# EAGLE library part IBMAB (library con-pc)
8-bit CARD IBM/PC-AT
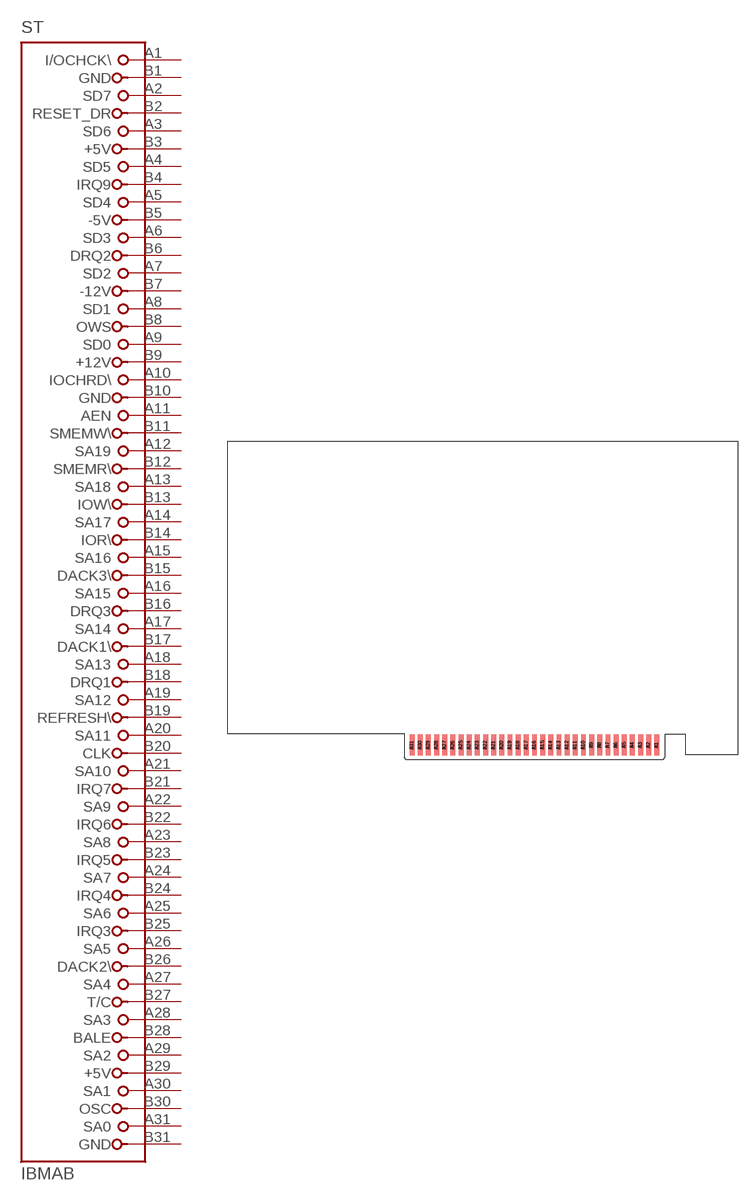
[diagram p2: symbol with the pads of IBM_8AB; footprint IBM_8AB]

Designator prefix ST

## IBMAB  [IBM_8AB]
A1  I/OCHCK\  in
A2  SD7
A3  SD6
A4  SD5
A5  SD4
A6  SD3
A7  SD2
A8  SD1
A9  SD0
A10  IOCHRD\  in
A11  AEN  out
A12  SA19
A13  SA18
A14  SA17
A15  SA16
A16  SA15
A17  SA14
A18  SA13
A19  SA12
A20  SA11
A21  SA10
A22  SA9
A23  SA8
A24  SA7
A25  SA6
A26  SA5
A27  SA4
A28  SA3
A29  SA2
A30  SA1
A31  SA0
B1  GND  pwr
B2  RESET_DR  out
B3  +5V  pwr
B4  IRQ9  in
B5  -5V  pwr
B6  DRQ2  in
B7  -12V  pwr
B8  OWS  in
B9  +12V  pwr
B10  GND  pwr
B11  SMEMW\  out
B12  SMEMR\  out
B13  IOW\
B14  IOR\
B15  DACK3\  out
B16  DRQ3  in
B17  DACK1\  out
B18  DRQ1  in
B19  REFRESH\
B20  CLK  out
B21  IRQ7  in
B22  IRQ6  in
B23  IRQ5  in
B24  IRQ4  in
B25  IRQ3  in
B26  DACK2\  out
B27  T/C  out
B28  BALE  out
B29  +5V  pwr
B30  OSC  out
B31  GND  pwr

## Footprint IBM_8AB (pad centres in mm)
8-bit CARD IBM/PC-AT
smd 1.524 x 6.477: A1 -25.4,5.08; A2 -27.94,5.08; A3 -30.48,5.08; A4 -33.02,5.08; A5 -35.56,5.08; A6 -38.1,5.08; A7 -40.64,5.08; A8 -43.18,5.08; A9 -45.72,5.08; A10 -48.26,5.08; A11 -50.8,5.08; A12 -53.34,5.08; A13 -55.88,5.08; A14 -58.42,5.08; A15 -60.96,5.08; A16 -63.5,5.08; A17 -66.04,5.08; A18 -68.58,5.08; A19 -71.12,5.08; A20 -73.66,5.08; A21 -76.2,5.08; A22 -78.74,5.08; A23 -81.28,5.08; A24 -83.82,5.08; A25 -86.36,5.08; A26 -88.9,5.08; A27 -91.44,5.08; A28 -93.98,5.08; A29 -96.52,5.08; A30 -99.06,5.08; A31 -101.6,5.08
smd 1.524 x 6.477 bottom: B1 -25.4,5.08; B2 -27.94,5.08; B3 -30.48,5.08; B4 -33.02,5.08; B5 -35.56,5.08; B6 -38.1,5.08; B7 -40.64,5.08; B8 -43.18,5.08; B9 -45.72,5.08; B10 -48.26,5.08; B11 -50.8,5.08; B12 -53.34,5.08; B13 -55.88,5.08; B14 -58.42,5.08; B15 -60.96,5.08; B16 -63.5,5.08; B17 -66.04,5.08; B18 -68.58,5.08; B19 -71.12,5.08; B20 -73.66,5.08; B21 -76.2,5.08; B22 -78.74,5.08; B23 -81.28,5.08; B24 -83.82,5.08; B25 -86.36,5.08; B26 -88.9,5.08; B27 -91.44,5.08; B28 -93.98,5.08; B29 -96.52,5.08; B30 -99.06,5.08; B31 -101.6,5.08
